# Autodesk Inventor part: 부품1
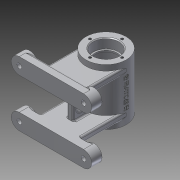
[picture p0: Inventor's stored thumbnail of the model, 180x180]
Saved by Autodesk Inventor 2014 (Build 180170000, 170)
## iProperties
Created: 2015-11
Part Number: 부품1
Material: 알루미늄 6061
Document SubType Name: Modeling
Designer: Owner
Mass: 358.154 g
Surface Area: 460.685 cm^2
Volume: 132.16 cm^3
Density: 2.71 g/cm^3
Appearance: 알루미늄 - 평지
Author: Owner
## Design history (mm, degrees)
sketch "스케치1"
  geometry: C1 r 25 at (0, 0); 1 further point
  constraints: 1 centre point, 1 coincident
  dimensions: "d0" = 50 diameter of C1
extrude "돌출1" new body sketch "스케치1" stored distance "d1" = 70; taper "d2" = 0 deg
sketch "스케치2"
  geometry: L1 (-25, -35)-(25, -35) reference; L2 (25, 35)-(-25, 35) reference; L3 (0, 0)-(0, -35); L4 (16, -35)-(16, -23); L5 (16, -23)-(14, -23); L6 (14, -23)-(14, -21); L7 (14, -21)-(21, -21); L8 (21, -21)-(21, 0); L9 (16, 35)-(16, 23); L10 (16, 23)-(14, 23); L11 (14, 23)-(14, 21); L12 (14, 21)-(21, 21); L13 (21, 21)-(21, 0); L14 (0, 0)-(0, 35); L15 (16, -35)-(16, -23); L16 (14, -23)-(14, -21); L17 (21, -21)-(14, -21); L18 (21, -21)-(21, 21); L19 (21, 21)-(14, 21); L20 (14, 23)-(14, 21); L21 (14, 21)-(21, 21); L22 (16, 23)-(16, 35); L23 (16, 35)-(0, 35); L24 (0, -35)-(16, -35)
  constraints: 44 end point, 6 parallel, 5 perpendicular, 4 collinear, 1 midpoint, 1 point on line
  dimensions: "d3" = 12 distance between parallel lines of L1 L5; "d4" = 2 distance between parallel lines of L5 L7; "d5" = 32 diameter of L4 L3; "d6" = 28 diameter of L6 L3; "d7" = 42 diameter of L8 L3
revolve "회전1" sketch "스케치2" stored, may be unused: angle "d8" = 90 deg
node "작업 평면1"
sketch "스케치3"
  geometry: L1 (0, -68)-(25, -68); L2 (25, -68)-(25, 0); L3 (-25, 0)-(-25, -68); L4 (-25, -68)-(0, -68); C1 r 16 at (0, 0) reference; C2 r 14 at (0, 0) reference; C3 r 25 at (0, 0); A1 r 25 centre (0, 0) between (25, 0) and (-25, 0) reference; 1 further point
  constraints: 8 end point, 2 equal length, 2 point on circle, 2 tangent, 1 centre point, 1 coincident
  dimensions: "d10" = 68 distance of C2.centre L1.start
extrude "돌출2" join sketch "스케치3" distance "d11" = 8; taper "d12" = 0 deg
node "작업 평면2"
sketch "스케치4"
  geometry: L1 (25, 20)-(-25, 20) reference; L2 (-25, 20)-(-25, 28) reference; L3 (25, 28)-(-25, 28) reference; L4 (25, 20)-(25, 28) reference; L5 (25, 20)-(40, 20); L6 (40, 40)-(-40, 40); L7 (-40, 20)-(-25, 20); L8 (25, 20)-(-25, 20); A1 r 10 centre (40, 30) between (40, 20) and (40, 40); A2 r 10 centre (-40, 30) between (-40, 40) and (-40, 20); 1 further point
  constraints: 8 end point, 4 point on circle, 4 tangent, 2 centre point, 2 collinear, 1 parallel, 1 perpendicular
extrude "돌출3" join sketch "스케치4" distance "d19" = 10; taper "d20" = 0 deg
sketch "스케치5"
  geometry: C1 r 10 at (40, -30); C2 r 10 at (-40, -30); A1 r 10 centre (-40, -30) between (-40, -20) and (-40, -40) reference; A2 r 10 centre (40, -30) between (40, -40) and (40, -20) reference; 1 further point
  constraints: 2 centre point, 2 coincident, 1 concentric
extrude "돌출4" join sketch "스케치5" distance "d21" = 3; taper "d22" = 0 deg
sketch "스케치6"
  geometry: C1 r 10 at (0, 0) reference; C2 r 10 at (-80, 0) reference; C3 r 6 at (0, 0); C4 r 6 at (-80, 0); 1 further point
  constraints: 2 centre point, 2 coincident
  dimensions: "d23" = 12 diameter of C3; "d24" = 12 diameter of C4
extrude "돌출5" cut sketch "스케치6" distance "d25" = 4; taper "d26" = 0 deg
sketch "스케치7"
  geometry: C1 r 6 at (0, 0) reference; C2 r 6 at (-80, 0) reference; C3 r 3 at (0, 0); C4 r 3 at (-80, 0); 1 further point
  constraints: 2 centre point, 2 coincident
  dimensions: "d27" = 6 diameter of C3; "d28" = 6 diameter of C4
extrude "돌출6" cut sketch "스케치7" stored distance "d29" = 4; taper "d30" = 0 deg
node "작업 평면3"
sketch "스케치9"
  geometry: L1 (-40, 20)-(40, 20) reference; L2 (40, 40)-(-40, 40) reference; L3 (0, 0)-(4, 0); L4 (4, 0)-(4, 20); L5 (0, 0)-(-4, 0); L6 (-4, 0)-(-4, 20); C1 r 3 at (-40, 30) reference; C2 r 3 at (40, 30) reference; A1 r 10 centre (-40, 30) between (-40, 40) and (-40, 20) reference; A2 r 10 centre (40, 30) between (40, 20) and (40, 40) reference
  constraints: 8 end point, 3 perpendicular, 2 point on line
  dimensions: "d32" = 4 distance of L3.start L3.end; "d33" = 4 distance of L3.start L5.end
extrude "돌출7" join sketch "스케치9" stored distance "d34" = 4; taper "d35" = 0 deg
sketch "스케치10"
  geometry: L1 (20, -23)-(0, -23) reference; L2 (-28, 13.5)-(-12, 13.5); L3 (-12, 6.5)-(-28, 6.5); A1 r 3.5 centre (-28, 10) between (-28, 13.5) and (-28, 6.5); A2 r 3.5 centre (-12, 10) between (-12, 6.5) and (-12, 13.5); 1 further point
  constraints: 4 end point, 4 point on circle, 4 tangent, 2 centre point, 1 parallel
  dimensions: "d40" = 7 distance of L3.start L2.end
extrude "돌출8" cut sketch "스케치10" stored distance "d41" = 4; taper "d42" = 0 deg
node "작업 평면4"
sketch "스케치11"
  geometry: C1 r 5 at (0, 0); 1 further point
  constraints: 1 centre point, 1 coincident
  dimensions: "d44" = 10 diameter of C1
extrude "돌출9" join sketch "스케치11" stored distance "d45" = 4; taper "d46" = 0 deg
sketch "스케치12"
  geometry: C1 r 5 at (0, 0) reference; 1 further point
  constraints: 1 coincident
hole "구멍1" sketch "스케치12" at (0, 0) diameter "d47" = 5.188; stored, may be unused: countersink angle "d51" = 90 deg, drill point angle "d53" = 118 deg; dims "d48" = 6, "d49" = 4, "d50" = 2, "d52" = 15
node "작업 평면6"
  node "작업 평면5"
sketch "스케치15"
  geometry: C1 r 25 at (0, 0) reference; A1 r 20 centre (0, 0) between (0, 20) and (20, 0); 2 further points
  constraints: 4 point on circle, 1 centre point, 1 coincident
  dimensions: "d66" = 40 diameter of A1
hole "구멍3" sketch "스케치15" at (0, 20), (20, 0), (0, -20), (-20, 0) diameter "d67" = 3.242; stored, may be unused: countersink angle "d71" = 90 deg, drill point angle "d73" = 118 deg; dims "d68" = 8, "d69" = 4, "d70" = 2, "d72" = 10
node "작업 평면7"
sketch "스케치16"
  geometry: L1 (25, -35)-(25, 35) reference; 2 further points
  constraints: 1 other
feature "엠보싱1" sketch "스케치16" dims "d0" = 50, "d3" = 12, "d4" = 2, "d5" = 32, "d6" = 28, "d7" = 42, "d75" = 0.5, "d76" = 0
fillet "모깎기1" dims "d77" = 0.3
fillet "모깎기2" dims "d78" = 3.5
fillet "모깎기3" dims "d79" = 3
fillet "모깎기4" dims "d80" = 2
fillet "모깎기5" dims "d81" = 2
chamfer "모따기1" distance "d82" = 1; stored, may be unused: second distance "d83" = 2, angle "d84" = 45 deg
node "작업 평면9"
  node "작업 평면8"
sketch "스케치17"
  geometry: C1 r 6 at (0, 0); 1 further point
  constraints: 1 centre point, 1 coincident
  dimensions: "d87" = 12 diameter of C1
extrude "돌출11" join sketch "스케치17" stored distance "d88" = 10; taper "d89" = 0 deg
sketch "스케치18"
  geometry: C1 r 6 at (0, 0) reference; 1 further point
  constraints: 1 coincident
hole "구멍4" sketch "스케치18" at (0, 0) diameter "d90" = 5.188; stored, may be unused: countersink angle "d94" = 90 deg, drill point angle "d96" = 118 deg; dims "d91" = 6, "d92" = 4, "d93" = 2, "d95" = 15
fillet "모깎기6" dims "d97" = 2
node "솔리드1"
mirror "대칭1"
mirror "대칭2"
node "투영된 루프1"
node "투영된 루프2"
node "투영된 루프3"
node "투영된 루프4"
node "투영된 루프5"
node "투영된 루프6"
other parameters: "d13" = -68, "d31" = -45, "d43" = 28, "d54" = 30 deg, "d55" = -28, "d74" = 25, "d85" = 60 deg, "d86" = -28
